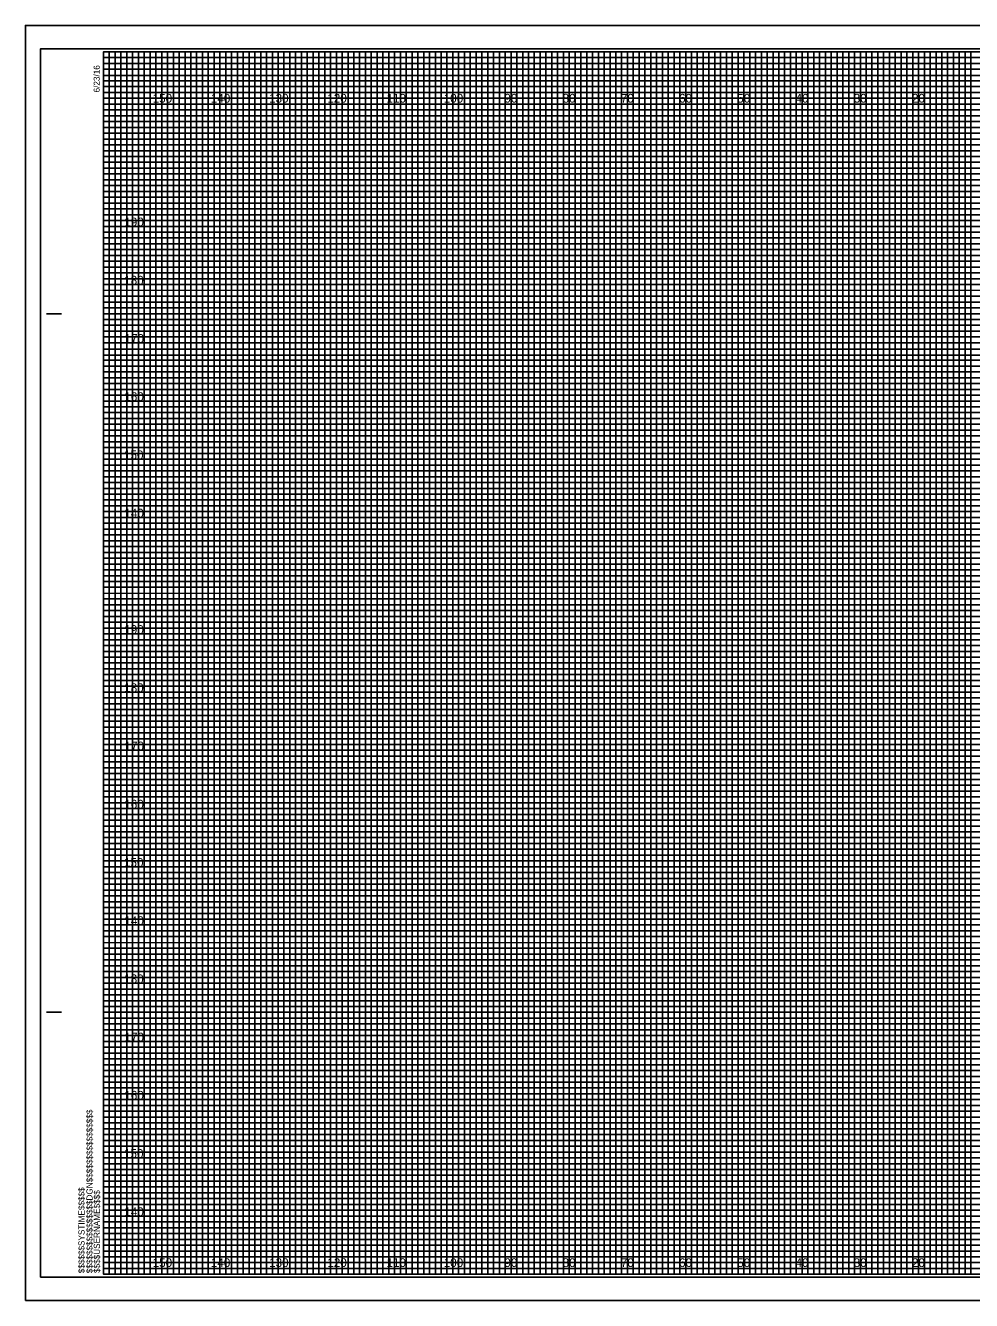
# Model space of a CAD drawing. Extents: x -13 to 323, y -5 to 654.
# Drawn here: x -13.4 to 149.1, y 215.5 to 434.5 of the extents above; entities that cross this region are included whole.
import ezdxf

# ---------------------------------------------------------------- set-up
doc = ezdxf.new("R2010")
doc.units = 0
for name, color, linetype in [('Exist Cross Section Cell', 7, 'Continuous'), ('Exist XS Center Line Elevation Label', 7, 'Continuous'), ('Exist XS Ground Line', 7, 'Continuous'), ('Prop CMT Guardrail Graphics', 7, 'Continuous'), ('Prop CMT Pvmt Course 1', 7, 'Continuous'), ('Prop CMT Pvmt Course 2', 7, 'Continuous'), ('Prop CMT Pvmt Course 3', 7, 'Continuous'), ('Prop CMT Shld Paved Course 1', 7, 'Continuous'), ('Prop CMT Shld Paved Course 2', 7, 'Continuous'), ('Prop CMT Subgrade Earthwork', 7, 'Continuous'), ('Scratch_Level_0', 7, 'Continuous')]:
    doc.layers.add(name, color=color, linetype=linetype)

msp = doc.modelspace()

# ---------------------------------------------------------------- linework, layer by layer
at = {"layer": 'Exist XS Center Line Elevation Label'}
for points in [[(0, 430), (5, 430), (5, 220), (15, 220), (15, 430), (25, 430), (25, 220), (35, 220), (35, 430), (45, 430), (45, 220), (55, 220), (55, 430), (65, 430), (65, 220), (75, 220), (75, 430), (85, 430), (85, 220), (95, 220), (95, 430), (105, 430), (105, 220), (115, 220), (115, 430), (125, 430), (125, 220), (135, 220), (135, 430), (145, 430), (145, 220), (155, 220)], [(0, 425), (275, 425)], [(0, 405), (320, 405), (320, 415), (0, 415)], [(0, 385), (320, 385), (320, 395), (0, 395)], [(0, 365), (320, 365), (320, 375), (0, 375)], [(0, 345), (320, 345), (320, 355), (0, 355)], [(0, 325), (320, 325), (320, 335), (0, 335)], [(0, 305), (320, 305), (320, 315), (0, 315)], [(0, 285), (320, 285), (320, 295), (0, 295)], [(0, 265), (320, 265), (320, 275), (0, 275)], [(0, 245), (320, 245), (320, 255), (0, 255)], [(0, 225), (320, 225), (320, 235), (0, 235)]]:
    msp.add_lwpolyline(points, dxfattribs=at)
at = {"layer": 'Exist XS Ground Line'}
for p, q in [((10, 430), (0, 430)), ((10, 220), (10, 430)), ((30, 430), (20, 430)), ((20, 430), (20, 220)), ((30, 220), (30, 430)), ((50, 430), (40, 430)), ((40, 430), (40, 220)), ((50, 220), (50, 430)), ((70, 430), (60, 430)), ((60, 430), (60, 220)), ((70, 220), (70, 430)), ((90, 430), (80, 430)), ((80, 430), (80, 220)), ((90, 220), (90, 430)), ((110, 430), (100, 430)), ((100, 430), (100, 220)), ((110, 220), (110, 430)), ((130, 430), (120, 430)), ((120, 430), (120, 220)), ((130, 220), (130, 430)), ((150, 430), (140, 430)), ((140, 430), (140, 220)), ((20, 220), (10, 220)), ((40, 220), (30, 220)), ((60, 220), (50, 220)), ((80, 220), (70, 220)), ((100, 220), (90, 220)), ((120, 220), (110, 220)), ((140, 220), (130, 220))]:
    msp.add_line(p, q, dxfattribs=at)
for points in [[(0, 420), (320, 420), (320, 410), (0, 410)], [(0, 400), (320, 400), (320, 390), (0, 390)], [(0, 380), (320, 380), (320, 370), (0, 370)], [(0, 360), (320, 360), (320, 350), (0, 350)], [(0, 340), (320, 340), (320, 330), (0, 330)], [(0, 320), (320, 320), (320, 310), (0, 310)], [(0, 300), (320, 300), (320, 290), (0, 290)], [(0, 280), (320, 280), (320, 270), (0, 270)], [(0, 260), (320, 260), (320, 250), (0, 250)], [(0, 240), (320, 240), (320, 230), (0, 230)]]:
    msp.add_lwpolyline(points, dxfattribs=at)
at = {"layer": 'Prop CMT Pvmt Course 1'}
for p, q in [((323.3, 434.5), (-13.4, 434.5)), ((-13.4, 434.5), (-13.4, 215.5)), ((-13.4, 215.5), (323.3, 215.5))]:
    msp.add_line(p, q, dxfattribs=at)
at = {"layer": 'Prop CMT Pvmt Course 2'}
msp.add_lwpolyline([(-13.4, 215.5), (323.3, 215.5), (323.3, 434.5), (-13.4, 434.5)], close=True, dxfattribs=at)
at = {"layer": 'Prop CMT Pvmt Course 3'}
msp.add_lwpolyline([(-10.8, 219.5), (322.4, 219.5), (322.4, 430.5), (-10.8, 430.5)], close=True, dxfattribs=at)
at = {"layer": 'Prop CMT Shld Paved Course 1'}
for p, q in [((-9.8, 385), (-7.3, 385)), ((-9.7, 385), (-7.2, 385)), ((-9.8, 265), (-7.3, 265)), ((-9.7, 265), (-7.2, 265)), ((0, 220), (0, 220)), ((0, 220), (0, 220)), ((0, 220), (0, 220)), ((0, 220), (0, 220)), ((0, 220), (0, 220)), ((0, 220), (0, 220)), ((0, 220), (0, 220))]:
    msp.add_line(p, q, dxfattribs=at)
msp.add_lwpolyline([(320, 430), (0, 430), (0, 220), (320, 220)], close=True, dxfattribs=at)
at = {"layer": 'Prop CMT Shld Paved Course 2'}
for points in [[(0, 220), (1, 220), (1, 430), (2, 430), (2, 220)], [(2, 220), (3, 220), (3, 430), (4, 430), (4, 220)], [(5, 220), (6, 220), (6, 430), (7, 430), (7, 220)], [(7, 220), (8, 220), (8, 430), (9, 430), (9, 220)], [(10, 220), (11, 220), (11, 430), (12, 430), (12, 220)], [(12, 220), (13, 220), (13, 430), (14, 430), (14, 220)], [(15, 220), (16, 220), (16, 430), (17, 430), (17, 220)], [(17, 220), (18, 220), (18, 430), (19, 430), (19, 220)], [(20, 220), (21, 220), (21, 430), (22, 430), (22, 220)], [(22, 220), (23, 220), (23, 430), (24, 430), (24, 220)], [(25, 220), (26, 220), (26, 430), (27, 430), (27, 220)], [(27, 220), (28, 220), (28, 430), (29, 430), (29, 220)], [(30, 220), (31, 220), (31, 430), (32, 430), (32, 220)], [(32, 220), (33, 220), (33, 430), (34, 430), (34, 220)], [(35, 220), (36, 220), (36, 430), (37, 430), (37, 220)], [(37, 220), (38, 220), (38, 430), (39, 430), (39, 220)], [(40, 220), (41, 220), (41, 430), (42, 430), (42, 220)], [(42, 220), (43, 220), (43, 430), (44, 430), (44, 220)], [(45, 220), (46, 220), (46, 430), (47, 430), (47, 220)], [(47, 220), (48, 220), (48, 430), (49, 430), (49, 220)], [(50, 220), (51, 220), (51, 430), (52, 430), (52, 220)], [(52, 220), (53, 220), (53, 430), (54, 430), (54, 220)], [(55, 220), (56, 220), (56, 430), (57, 430), (57, 220)], [(57, 220), (58, 220), (58, 430), (59, 430), (59, 220)], [(60, 220), (61, 220), (61, 430), (62, 430), (62, 220)], [(62, 220), (63, 220), (63, 430), (64, 430), (64, 220)], [(65, 220), (66, 220), (66, 430), (67, 430), (67, 220)], [(67, 220), (68, 220), (68, 430), (69, 430), (69, 220)], [(70, 220), (71, 220), (71, 430), (72, 430), (72, 220)], [(72, 220), (73, 220), (73, 430), (74, 430), (74, 220)], [(75, 220), (76, 220), (76, 430), (77, 430), (77, 220)], [(77, 220), (78, 220), (78, 430), (79, 430), (79, 220)], [(80, 220), (81, 220), (81, 430), (82, 430), (82, 220)], [(82, 220), (83, 220), (83, 430), (84, 430), (84, 220)], [(85, 220), (86, 220), (86, 430), (87, 430), (87, 220)], [(87, 220), (88, 220), (88, 430), (89, 430), (89, 220)], [(90, 220), (91, 220), (91, 430), (92, 430), (92, 220)], [(92, 220), (93, 220), (93, 430), (94, 430), (94, 220)], [(95, 220), (96, 220), (96, 430), (97, 430), (97, 220)], [(97, 220), (98, 220), (98, 430), (99, 430), (99, 220)], [(100, 220), (101, 220), (101, 430), (102, 430), (102, 220)], [(102, 220), (103, 220), (103, 430), (104, 430), (104, 220)], [(105, 220), (106, 220), (106, 430), (107, 430), (107, 220)], [(107, 220), (108, 220), (108, 430), (109, 430), (109, 220)], [(110, 220), (111, 220), (111, 430), (112, 430), (112, 220)], [(112, 220), (113, 220), (113, 430), (114, 430), (114, 220)], [(115, 220), (116, 220), (116, 430), (117, 430), (117, 220)], [(117, 220), (118, 220), (118, 430), (119, 430), (119, 220)], [(120, 220), (121, 220), (121, 430), (122, 430), (122, 220)], [(122, 220), (123, 220), (123, 430), (124, 430), (124, 220)], [(125, 220), (126, 220), (126, 430), (127, 430), (127, 220)], [(127, 220), (128, 220), (128, 430), (129, 430), (129, 220)], [(130, 220), (131, 220), (131, 430), (132, 430), (132, 220)], [(132, 220), (133, 220), (133, 430), (134, 430), (134, 220)], [(135, 220), (136, 220), (136, 430), (137, 430), (137, 220)], [(137, 220), (138, 220), (138, 430), (139, 430), (139, 220)], [(140, 220), (141, 220), (141, 430), (142, 430), (142, 220)], [(142, 220), (143, 220), (143, 430), (144, 430), (144, 220)], [(145, 220), (146, 220), (146, 430), (147, 430), (147, 220)], [(147, 220), (148, 220), (148, 430), (149, 430), (149, 220)]]:
    msp.add_lwpolyline(points, dxfattribs=at)
at = {"layer": 'Prop CMT Subgrade Earthwork'}
for p, q in [((10, 220), (10, 430)), ((20, 220), (20, 430)), ((30, 220), (30, 430)), ((40, 220), (40, 430)), ((50, 220), (50, 430)), ((60, 220), (60, 430)), ((70, 220), (70, 430)), ((80, 220), (80, 430)), ((90, 220), (90, 430)), ((100, 220), (100, 430)), ((110, 220), (110, 430)), ((120, 220), (120, 430)), ((130, 220), (130, 430)), ((140, 220), (140, 430)), ((0, 420), (320, 420)), ((0, 410), (320, 410)), ((0, 400), (320, 400)), ((0, 390), (320, 390)), ((0, 380), (320, 380)), ((0, 370), (320, 370)), ((0, 360), (320, 360)), ((0, 350), (320, 350)), ((0, 340), (320, 340)), ((0, 330), (320, 330)), ((0, 320), (320, 320)), ((0, 310), (320, 310)), ((0, 300), (320, 300)), ((0, 290), (320, 290)), ((0, 280), (320, 280)), ((0, 270), (320, 270)), ((0, 260), (320, 260)), ((0, 250), (320, 250)), ((0, 240), (320, 240)), ((0, 230), (320, 230))]:
    msp.add_line(p, q, dxfattribs=at)
at = {"layer": 'Scratch_Level_0'}
for p, q in [((0, 429), (260, 429)), ((260, 427.98), (0, 427.98)), ((0, 427.98), (0, 427)), ((0, 427), (260, 427)), ((260, 425.89), (0, 425.89)), ((0, 425.89), (0, 424)), ((0, 424), (320, 424))]:
    msp.add_line(p, q, dxfattribs=at)
for points in [[(0, 423), (270, 423), (320, 423), (320, 422), (0, 422)], [(0, 421), (320, 421), (320, 419), (0, 419)], [(0, 418), (320, 418), (320, 417), (0, 416.98)], [(0, 416), (320, 416), (320, 414), (0, 414)], [(0, 413), (320, 413), (320, 412), (0, 412)], [(0, 411), (320, 411), (320, 409), (0, 409)], [(0, 408), (320, 408), (320, 407), (0, 407)], [(0, 406), (320, 406), (320, 404), (0, 404)], [(0, 403), (320, 403), (320, 402), (0, 402)], [(0, 401), (320, 401), (320, 399), (0, 399)], [(0, 398), (320, 398), (320, 397), (0, 397)], [(0, 396), (320, 396), (320, 393.95), (320, 393), (320, 392), (0, 392)], [(0, 394), (320, 394), (320, 393), (0, 393)], [(0, 391), (320, 391), (320, 389), (0, 389.03)], [(0, 389.03), (320, 389), (320, 388), (0, 388)], [(0, 387), (320, 387), (320, 386), (0, 386)], [(0, 384), (320, 384), (320, 383), (0, 383)], [(0, 382), (320, 382), (320, 381), (0, 381)], [(-0.07, 378.89), (320, 378.89), (320, 377.88), (-0.07, 377.88)], [(0, 377), (320, 377), (320, 376), (0, 376)], [(0, 374), (320, 374), (320, 373), (0, 373)], [(0, 372), (320, 372), (320, 371), (0, 371)], [(0, 369), (320, 369), (320, 368), (0, 368)], [(0, 367), (320, 367), (320, 366), (0, 366)], [(0, 364), (320, 364), (320, 363), (0, 363)], [(0, 362), (320, 362), (320, 361), (0, 361)], [(0, 359), (320, 359), (319.99, 357.98), (0, 358)], [(0, 357), (320, 357), (320, 356), (0, 356)], [(0, 354), (320, 354), (320, 353), (0, 353)], [(0, 352), (320, 352), (320, 351), (0, 351)], [(0, 349), (320, 349), (320, 348), (0, 348)], [(0, 347), (320, 347), (320, 346), (0, 346)], [(0, 344), (320, 344), (320, 343), (0, 343)], [(0, 342), (320, 342), (320, 341), (0, 341)], [(0, 339), (320, 339), (320, 338), (0, 338)], [(0, 336.99), (320.07, 336.91), (320, 336), (0, 336)], [(0, 334), (320, 334), (320, 333), (0, 333)], [(0, 332), (320, 332), (320, 331), (0, 331)], [(0, 329), (320, 329), (320, 328), (0, 328)], [(0, 327), (320, 327), (320, 326), (0, 326)], [(0, 324), (320, 324), (320, 323), (0, 323)], [(0, 322), (320, 322), (320, 321), (0, 321)], [(0, 319), (320, 319), (320, 318), (0, 318)], [(0, 317), (320, 317), (320, 316), (0, 316)], [(0, 314), (320, 314), (320, 313), (0, 313)], [(0, 312), (320, 312), (320, 311), (0, 311)], [(0, 309), (320, 309), (320, 308), (0, 308)], [(0, 307), (320, 307), (320, 306), (0, 306)], [(0, 304), (320, 304), (320, 303), (0, 303)], [(0, 302), (320, 302), (320, 301), (0, 301)], [(0, 299), (320, 299), (319.99, 297.98), (0, 298)], [(0, 297), (320, 297), (320, 296), (0, 296)], [(0, 294), (320, 294), (320, 293), (0, 293)], [(0, 292), (320, 292), (320, 291), (0, 291)], [(0, 289), (320, 289), (320, 288), (0, 288)], [(0, 287), (320, 287), (320, 286), (0, 286)], [(0, 284), (320, 284), (320, 283), (0, 283)], [(0, 282), (320, 282), (320, 281), (0, 281)], [(0, 279), (320, 279), (320, 278), (0, 278)], [(0, 276.99), (320.07, 276.91), (320, 276), (0, 276)], [(0, 274), (320, 274), (320, 273), (0, 273)], [(0, 272), (320, 272), (320, 271), (0, 271)], [(0, 269), (320, 269), (320, 268), (0, 268)], [(0, 267), (320, 267), (320, 266), (0, 266)], [(0, 264), (320, 264), (320, 263), (0, 263)], [(0, 262), (320, 262), (320, 261), (0, 261)], [(0, 259), (320, 259), (320, 258), (0, 258)], [(0, 257), (320, 257), (320, 256), (0, 256)], [(0, 254), (320, 254), (320, 253), (0, 253)], [(0, 252), (320, 252), (320, 251), (0, 251)], [(0, 249), (320, 249), (320, 248), (0, 248)], [(0, 247), (320, 247), (320, 246), (0, 246)], [(0, 244), (320, 244), (320, 243), (0, 243)], [(0, 242), (320, 242), (320, 241), (0, 241)], [(0, 239), (320, 239), (320, 238), (0, 238)], [(0, 237), (320, 237), (320, 236), (0, 236)], [(0, 234), (320, 234), (320, 233), (0, 233)], [(0, 232), (320, 232), (320, 231), (0, 231)], [(0, 229), (320, 229), (320, 228), (0, 228)], [(0, 227), (320, 227), (320, 226), (0, 226)], [(0, 224), (320, 224), (320, 223), (0, 223)], [(0, 222), (320, 222), (320, 221), (0, 221)]]:
    msp.add_lwpolyline(points, dxfattribs=at)

# ---------------------------------------------------------------- texts
at = {"layer": 'Exist Cross Section Cell'}
for s, p in [('150', (8.44, 421.25)), ('140', (18.44, 421.25)), ('130', (28.44, 421.25)), ('120', (38.44, 421.25)), ('110', (48.62, 421.25)), ('100', (58.44, 421.25)), ('90', (68.86, 421.25)), ('80', (78.86, 421.25)), ('70', (88.86, 421.25)), ('60', (98.86, 421.25)), ('50', (108.86, 421.25)), ('40', (118.86, 421.25)), ('30', (128.86, 421.25)), ('20', (138.86, 421.25)), ('150', (8.44, 221.25)), ('140', (18.44, 221.25)), ('130', (28.44, 221.25)), ('120', (38.44, 221.25)), ('110', (48.62, 221.25)), ('100', (58.44, 221.25)), ('90', (68.86, 221.25)), ('80', (78.86, 221.25)), ('70', (88.86, 221.25)), ('60', (98.86, 221.25)), ('50', (108.86, 221.25)), ('40', (118.86, 221.25)), ('30', (128.86, 221.25)), ('20', (138.86, 221.25))]:
    msp.add_text(s, height=1.5, dxfattribs=at).set_placement(p)
at = {"layer": 'Prop CMT Guardrail Graphics'}
for s, p in [('190', (3.57, 400)), ('180', (3.55, 390)), ('170', (3.61, 380)), ('160', (3.57, 370)), ('150', (3.52, 360)), ('140', (3.57, 350)), ('190', (3.57, 330)), ('180', (3.55, 320)), ('170', (3.61, 310)), ('160', (3.57, 300)), ('150', (3.52, 290)), ('140', (3.57, 280)), ('180', (3.55, 270)), ('170', (3.61, 260)), ('160', (3.57, 250)), ('150', (3.52, 240)), ('140', (3.57, 230))]:
    msp.add_text(s, height=1.5, dxfattribs=at).set_placement(p)
at = {"layer": 'Prop CMT Shld Paved Course 1'}
for s, p in [('6/23/16', (-0.65, 423)), ('$$$$$$$$$$$$$$$$DGN$$$$$$$$$$$$$$$$', (-1.88, 220.18)), ('$$$$$$SYSTIME$$$$$', (-3.26, 220.18)), ('$$$$USERNAME$$$$', (-0.62, 220.23))]:
    msp.add_text(s, height=1.05, rotation=90, dxfattribs=at).set_placement(p)

doc.saveas('drawing.dxf')
